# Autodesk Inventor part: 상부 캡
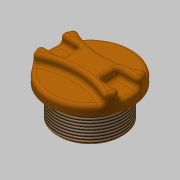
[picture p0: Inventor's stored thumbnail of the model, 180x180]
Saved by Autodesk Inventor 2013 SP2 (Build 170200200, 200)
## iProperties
Created: 2016-09
Part Number: 상부 캡
Material: PC/ABS 플라스틱
Document SubType Name: Modeling
Designer: mduedu
Density: 1.493 g/cm^3
Author: mduedu
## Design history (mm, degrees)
sketch "스케치1"
  geometry: C1 r 22.5 at (0, 0); 1 further point
  constraints: 1 centre point, 1 coincident
  dimensions: "d0" = 45 diameter of C1
extrude "돌출1" new body sketch "스케치1" distance "d1" = 10; taper "d2" = 0 deg
sketch "스케치2" dims "d4" = 80
  geometry: C1 r 22.5 at (0, 0) reference; 3 further points
  constraints: 3 vertical alignment, 2 other
  dimensions: "d3" = 7 distance of point (0, 7) point (0, 0)
extrude "돌출2" cut sketch "스케치2" distance "d5" = 5; taper "d6" = 0 deg
sketch "스케치3"
  geometry: L1 (-22.5, 0)-(0, 0); L2 (-21.937, 5)-(-10, 5); L3 (-10, 5)-(-10, -5); L4 (-10, -5)-(-21.937, -5); A1 r 22.5 centre (0, 0) between (-19.118, 11.864) and (-19.118, -11.864) reference; A2 r 22.5 centre (0, 0) between (-21.937, 5) and (-21.937, -5); 1 further point
  constraints: 8 end point, 5 point on circle, 2 horizontal, 1 centre point, 1 coincident, 1 parallel, 1 perpendicular, 1 symmetric about line
  dimensions: "d7" = 10 distance from line of L3 point (0, 0); "d8" = 10 distance of L2.end L3.end
extrude "돌출3" cut sketch "스케치3" distance "d9" = 5; taper "d10" = 0 deg
fillet "모깎기1" dims "d11" = 2
fillet "모깎기2" dims "d12" = 2
fillet "모깎기3" dims "d13" = 2
sketch "스케치4"
  geometry: C1 r 17.5 at (0, 0); 1 further point
  constraints: 1 centre point, 1 coincident
  dimensions: "d14" = 35 diameter of C1
extrude "돌출4" join sketch "스케치4" distance "d15" = 17; taper "d16" = 0 deg
sketch "스케치5"
  geometry: C1 r 12.5 at (0, 0); 1 further point
  constraints: 1 centre point, 1 coincident
  dimensions: "d17" = 25 diameter of C1
extrude "돌출5" cut sketch "스케치5" distance "d18" = 10; taper "d19" = 0 deg
fillet "모깎기4" dims "d20" = 3
feature "스레드1" dims "d21" = 10, "d22" = 0
chamfer "모따기1" distance "d23" = 1; stored, may be unused: second distance "d24" = 2, angle "d25" = 45 deg
node "솔리드1"
mirror "대칭1"
mirror "대칭2"
node "투영된 루프1"
